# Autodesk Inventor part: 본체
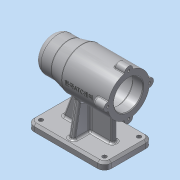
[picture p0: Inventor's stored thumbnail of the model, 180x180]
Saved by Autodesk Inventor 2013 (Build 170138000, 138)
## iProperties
Created: 2019-07
Part Number: 본체
Material: 알루미늄 6061
Document SubType Name: Modeling
Designer: dg
Mass: 651.004 g
Surface Area: 657.622 cm^2
Volume: 240.223 cm^3
Density: 2.71 g/cm^3
Author: dg
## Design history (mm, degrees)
sketch "스케치1"
  geometry: L1 (-56, -35)-(56, -35); L2 (56, -35)-(56, 35); L3 (56, 35)-(-56, 35); L4 (-56, 35)-(-56, -35); L5 (-56, -35)-(56, 35); L6 (56, -35)-(-56, 35); 1 further point
  constraints: 12 end point, 2 midpoint, 2 parallel, 1 horizontal, 1 perpendicular
  dimensions: "d0" = 112 distance of L2.end L3.end; "d2" = 70 distance of L1.end L2.end
extrude "돌출1" new body sketch "스케치1" distance "d3" = 10; taper "d4" = 0 deg
fillet "모깎기1" dims "d5" = 10
sketch "스케치2"
  geometry: A1 r 10 centre (46, -25) between (46, -35) and (56, -25) reference; A2 r 10 centre (46, 25) between (56, 25) and (46, 35) reference; A3 r 10 centre (-46, 25) between (-46, 35) and (-56, 25) reference; A4 r 10 centre (-46, -25) between (-56, -25) and (-46, -35) reference; 1 further point
hole "구멍1" sketch "스케치2" at (-46, 25), (46, 25), (46, -25), (-46, -25) diameter "d6" = 6; stored, may be unused: countersink angle "d10" = 90 deg, drill point angle "d12" = 118 deg; dims "d7" = 6, "d8" = 4, "d9" = 2, "d11" = 10
node "작업 평면1"
sketch "스케치4"
  geometry: L1 (-10, 0)-(-10, 10) reference; L2 (-10, 10)-(0, 10) reference; L3 (0, 10)-(0, 0) reference; L4 (0, 0)-(-10, 0) reference; L5 (-10, 0)-(-10, 10) reference; L6 (92, 0)-(92, 10) reference; L7 (92, 0)-(0, 0) reference; L8 (0, 10)-(0, 0) reference; L9 (92, 10)-(0, 10) reference; L10 (92, 0)-(92, 10) reference; L11 (92, 10)-(102, 10) reference; L12 (102, 10)-(102, 0) reference; L13 (102, 0)-(92, 0) reference; L14 (92, 0)-(92, 10) reference; L15 (102, 0)-(102, 80); L16 (102, 80)-(-10, 80); L17 (-10, 80)-(-10, 105); L18 (-10, 105)-(15, 105); L19 (15, 105)-(35, 110); L20 (35, 110)-(102, 110); L21 (102, 110)-(102, 80); 1 further point
  constraints: 14 end point, 3 parallel, 3 perpendicular
  dimensions: "d51" = 80 distance of L12.end L15.end; "d57" = 50 diameter of L18 L16; "d58" = 60 diameter of L20 L16; "d60" = 25 distance from line of L18.end L17; "d61" = 45 distance from line of L19.end L17; "d62" = 112 distance of L15.end L16.end
revolve "회전1" sketch "스케치4" stored, may be unused: angle "d65" = 90 deg
fillet "모깎기2" dims "d66" = 10
sketch "스케치5"
  geometry: C1 r 30 at (0, 0) reference; C2 r 21 at (0, 0); 1 further point
  constraints: 1 centre point, 1 coincident
  dimensions: "d67" = 42 diameter of C2
extrude "돌출2" cut sketch "스케치5" distance "d69" = 15; taper "d70" = 0 deg
sketch "스케치6"
  geometry: C1 r 21 at (0, 0) reference; C2 r 24 at (0, 0); 1 further point
  constraints: 1 centre point, 1 coincident
  dimensions: "d71" = 48 diameter of C2
extrude "돌출3" cut sketch "스케치6" distance "d74" = 54; taper "d75" = 0 deg
sketch "스케치7"
  geometry: C1 r 24 at (0, 0) reference; C2 r 21 at (0, 0); 1 further point
  constraints: 1 centre point, 1 coincident
  dimensions: "d76" = 42 diameter of C2
extrude "돌출4" cut sketch "스케치7" distance "d78" = 12; taper "d79" = 0 deg
sketch "스케치8"
  geometry: C1 r 21 at (0, 0) reference; C2 r 17.5 at (0, 0); 1 further point
  constraints: 1 centre point, 1 coincident
  dimensions: "d80" = 35 diameter of C2
extrude "돌출5" cut sketch "스케치8" distance "d82" = 18; taper "d83" = 0 deg
sketch "스케치9"
  geometry: C1 r 17.5 at (0, 0) reference; C2 r 16 at (0, 0); 1 further point
  constraints: 1 centre point, 1 coincident
  dimensions: "d84" = 32 diameter of C2
extrude "돌출6" cut sketch "스케치9" distance "d86" = 4; taper "d87" = 0 deg
sketch "스케치10"
  geometry: C1 r 16 at (0, 0) reference; C2 r 10.5 at (0, 0); 1 further point
  constraints: 1 centre point, 1 coincident
  dimensions: "d88" = 21 diameter of C2
extrude "돌출7" cut sketch "스케치10" distance "d90" = 3; taper "d91" = 0 deg
fillet "모깎기3" dims "d92" = 3
fillet "모깎기4" dims "d93" = 3
fillet "모깎기5" dims "d94" = 0.3
fillet "모깎기6" dims "d95" = 3
sketch "스케치11"
  geometry: L1 (0, 0)-(-30, 0); C1 r 6 at (-30, 0); 1 further point
  constraints: 2 end point, 1 centre point, 1 coincident, 1 horizontal, 1 horizontal alignment, 1 other
  dimensions: "d97" = 6 radius of C1
extrude "돌출8" join sketch "스케치11" distance "d99" = 16; taper "d100" = 0 deg
fillet "모깎기7" dims "d101" = 3
fillet "모깎기8" dims "d102" = 1
sketch "스케치12"
  geometry: A1 r 6 centre (0, 0) between (-0.171, 5.998) and (-0.171, -5.998) reference; 1 further point
hole "구멍2" sketch "스케치12" at (0, 0) diameter "d103" = 3.242; stored, may be unused: countersink angle "d107" = 90 deg, drill point angle "d109" = 118 deg; dims "d104" = 8, "d105" = 4, "d106" = 2, "d108" = 11
fillet "모깎기9" dims "d113" = 3
fillet "모깎기10" dims "d114" = 1
sketch "스케치13"
  geometry: L1 (15.358, 105.09)-(15.358, 54.91) reference; L2 (34.642, 50.09)-(34.642, 109.91) reference; L3 (0, 105)-(0, 55) reference; L4 (14.631, 55)-(14.631, 105) reference; L5 (102, 86.771)-(89, 86.771) reference; L6 (102, 109.226)-(102, 86.771) reference; L7 (89, 109.226)-(102, 109.226) reference; L8 (85, 109.871)-(85, 109.871) reference; L9 (102, 109.226)-(89, 109.226) reference; L10 (102, 86.771)-(102, 109.226) reference; L11 (89, 86.771)-(102, 86.771) reference; L12 (85, 77.221)-(85, 82.779) reference; L13 (102, 73.229)-(89, 73.229) reference; L14 (102, 50.774)-(102, 73.229) reference; L15 (89, 50.774)-(102, 50.774) reference; L16 (85, 50.129)-(85, 50.129) reference; L17 (102, 50.774)-(89, 50.774) reference; L18 (102, 73.229)-(102, 50.774) reference; L19 (89, 73.229)-(102, 73.229) reference; L20 (85, 82.779)-(85, 77.221) reference; L21 (35.369, 110)-(35.369, 50) reference; L22 (92, 0)-(92, 10) reference; L23 (92, 0)-(0, 0) reference; L24 (0, 10)-(0, 0) reference; L25 (92, 10)-(0, 10) reference; L26 (-10, 10)-(0, 10) reference; L27 (0, 10)-(0, 0) reference; L28 (0, 0)-(-10, 0) reference; L29 (-10, 0)-(-10, 10) reference; L30 (92, 10)-(102, 10) reference; L31 (102, 10)-(102, 0) reference; L32 (102, 0)-(92, 0) reference; L33 (92, 0)-(92, 10) reference; L34 (35.369, 110)-(85, 110) reference; L35 (35.369, 50)-(85, 50) reference; L36 (15.358, 54.91)-(34.642, 50.09) reference; L37 (0, 55)-(14.631, 55) reference; L38 (26.015, 54)-(10, 10); L39 (26.015, 54)-(82, 54); L40 (82, 54)-(82, 10); L41 (82, 10)-(10, 10); 1 further point
  constraints: 8 end point, 2 point on line, 1 collinear, 1 parallel, 1 perpendicular, 8 other
  dimensions: "d115" = 20 distance between parallel lines of L31 L40; "d116" = 20 distance from line of L29 L38.end; "d117" = 110 deg angle of L26 L38; "d118" = 44 distance between parallel lines of L25 L39
extrude "돌출9" join sketch "스케치13" stored distance "d119" = 8; taper "d120" = 0 deg
node "작업 평면2"
sketch "스케치14"
  geometry: L1 (-10, 47)-(-10, 53) reference; L2 (-10, 50)-(-10, 60) reference; L3 (0, 53)-(-10, 53) reference; L4 (-10, 50)-(-10, 60) reference; L5 (-10, 60)-(0, 60) reference; L6 (0, 60)-(0, 50) reference; L7 (0, 50)-(-10, 50) reference; L8 (0, 50)-(-10, 50) reference; L9 (0, 50)-(0, 0) reference; L10 (-10, 0)-(0, 0) reference; L11 (-10, 50)-(-10, 0) reference; L12 (-10, -10)-(-10, 0) reference; L13 (-10, 0)-(0, 0) reference; L14 (0, 0)-(0, -10) reference; L15 (0, -10)-(-10, -10) reference; L16 (-52.659, 21)-(-10, 21) reference; L17 (-10, 29)-(-52.659, 29) reference; L18 (-57.334, 5.346)-(-10, -3); L19 (-10, -3)-(-10, 53); L20 (-57.334, 44.654)-(-10, 53); A1 r 30 centre (-80, 25) between (-50.268, 29) and (-50.268, 21) reference; A2 r 30 centre (-80, 25) between (-57.334, 5.346) and (-57.334, 44.654); 1 further point
  constraints: 6 end point, 3 point on circle, 2 point on line, 1 centre point, 1 coincident
  dimensions: "d125" = 7 distance from line of L5 L19.end; "d126" = 7 distance from line of L15 L18.end; "d127" = 100 deg angle of L2 L20; "d128" = 100 deg angle of L11 L18
extrude "돌출10" join sketch "스케치14" stored distance "d132" = 8; taper "d133" = 0 deg
fillet "모깎기11" dims "d134" = 3
fillet "모깎기12" dims "d135" = 3
chamfer "모따기1" distance "d136" = 1; stored, may be unused: second distance "d137" = 2, angle "d138" = 45 deg
chamfer "모따기2" distance "d139" = 3; stored, may be unused: second distance "d140" = 2, angle "d141" = 45 deg
node "작업 평면3"
sketch "스케치15"
  geometry: L1 (56, 86.771)-(56, 109.226) reference; L2 (56, 58)-(56, 102) reference; L3 (56, 50.774)-(56, 73.229) reference; L4 (56, 80)-(-28, 80); L5 (56, 116)-(56, 110.171) reference; 3 further points
  constraints: 2 coincident, 2 end point, 2 midpoint, 1 perpendicular, 1 other
  dimensions: "d143" = 42 distance from line of point (14, 80) L5
feature "엠보싱1" sketch "스케치15" dims "d144" = 0.5, "d145" = 0
node "솔리드1"
pattern_circular "원형 패턴1" dims angle "d111" = 360 deg
node "투영된 루프1"
node "투영된 루프2"
node "투영된 루프3"
node "투영된 루프4"
node "투영된 루프5"
node "투영된 루프6"
node "투영된 루프7"
node "투영된 루프8"
node "투영된 루프9"
node "투영된 루프10"
node "투영된 루프11"
node "투영된 루프12"
